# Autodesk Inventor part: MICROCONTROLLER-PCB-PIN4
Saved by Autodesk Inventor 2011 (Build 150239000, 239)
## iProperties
Created: 2007-09
Part Number: MICROCONTROLLER-PCB-PIN4
Document SubType Name: Modeling
Density: 1 g/cm^3
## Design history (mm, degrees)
feature "Base1"
body "Solid1"
